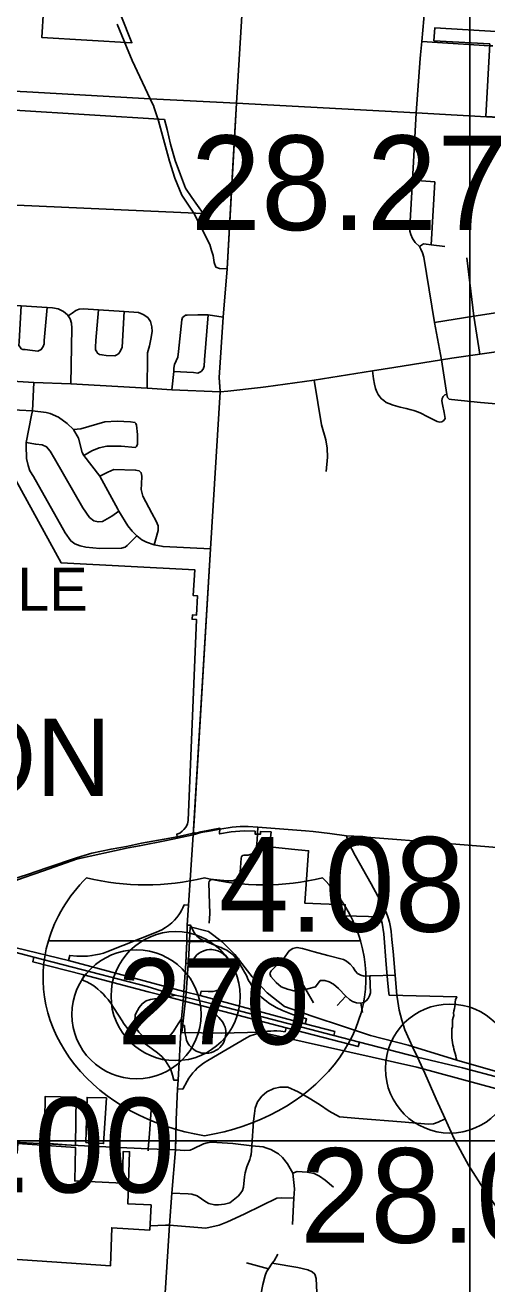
# Model space of a CAD drawing. Extents: x 1659811 to 1934326, y 644115 to 934867.
# Drawn here: x 1840906 to 1846268, y 763835 to 778471 of the extents above; entities that cross this region are included whole.
import ezdxf

# ---------------------------------------------------------------- set-up
doc = ezdxf.new("R2010")
doc.units = 0
for name, color, linetype in [('Default', 7, 'Continuous'), ('GM_X_City_Street', 7, 'Continuous'), ('GM_X_Corporation', 7, 'Continuous'), ('GM_X_Corporation_Text', 7, 'Continuous'), ('GM_X_County', 7, 'Continuous'), ('GM_X_County_Road', 7, 'Continuous'), ('GM_X_Interchange_Ramps', 7, 'Continuous'), ('GM_X_Interstate_Route', 7, 'Continuous'), ('GM_X_Interstate_Shield', 7, 'Continuous'), ('GM_X_State_Route', 7, 'Continuous'), ('GM_X_Township', 7, 'Continuous'), ('GM_X_Township_Road', 7, 'Continuous'), ('GM_X_Township_Text', 7, 'Continuous'), ('SC_Scratch1', 7, 'Continuous'), ('SH_Text', 7, 'Continuous')]:
    doc.layers.add(name, color=color, linetype=linetype)

msp = doc.modelspace()

# ---------------------------------------------------------------- linework, layer by layer
at = {"layer": 'Default'}
for centre in [(1842653, 767180), (1842199, 766968), (1845840, 766338)]:
    msp.add_circle(centre, 750, dxfattribs=at)
at = {"layer": 'GM_X_City_Street'}
for points in [[(1843361, 777564), (1843430, 778709), (1843626, 781866)], [(1845497, 778125), (1845512, 778280), (1845535, 778545), (1845550, 778898), (1845665, 780916), (1845701, 781367)], [(1842083, 778219), (1842149, 778061), (1842358, 777614)], [(1845512, 778280), (1846301, 778231), (1846340, 778229)], [(1845449, 777453), (1845493, 778084), (1845497, 778125)], [(1842402, 777520), (1842400, 777525), (1842358, 777614)], [(1843319, 776835), (1843361, 777564)], [(1845741, 774579), (1845662, 775012), (1845535, 775772), (1845521, 775824), (1845502, 775866), (1845486, 775898), (1845438, 775942), (1845404, 775990), (1845385, 776036), (1845376, 776077), (1845374, 776122), (1845405, 776668), (1845449, 777453)], [(1843251, 775637), (1843319, 776835)], [(1845621, 775918), (1845663, 776648), (1845405, 776668)], [(1843021, 775979), (1843015, 775989), (1842867, 776284), (1842796, 776391)], [(1843251, 775637), (1843165, 775642), (1843121, 775659), (1843101, 775711), (1843088, 775791), (1843071, 775852), (1843051, 775922), (1843021, 775979)], [(1845486, 775898), (1845532, 775927), (1845565, 775926), (1845621, 775918), (1845779, 775896)], [(1846187, 774646), (1846119, 775087), (1846036, 775766)], [(1843170, 774216), (1843158, 774374), (1843206, 775074), (1843251, 775637)], [(1839970, 775238), (1840262, 775243), (1840564, 775225), (1840861, 775207), (1841162, 775189), (1841222, 775185), (1841290, 775172), (1841353, 775141), (1841397, 775101), (1841404, 775090), (1841428, 775058), (1841443, 775004), (1841449, 774946), (1841435, 774301)], [(1840861, 775207), (1840838, 774791), (1840833, 774747), (1840847, 774725), (1840861, 774709), (1840880, 774698), (1840904, 774698), (1840962, 774691)], [(1840962, 774691), (1841054, 774682), (1841092, 774698), (1841116, 774734), (1841127, 774766), (1841127, 774804), (1841162, 775189)], [(1841404, 775090), (1841453, 775122), (1841493, 775154), (1841535, 775169), (1841581, 775171), (1841757, 775160), (1842056, 775141), (1842222, 775131), (1842275, 775106), (1842331, 775070), (1842360, 775025), (1842379, 774963), (1842383, 774909), (1842366, 774821), (1842349, 774743), (1842328, 774659), (1842327, 774615), (1842324, 774250)], [(1841848, 774629), (1841798, 774638), (1841770, 774642), (1841746, 774656), (1841737, 774674), (1841723, 774695), (1841721, 774727), (1841726, 774805), (1841757, 775160)], [(1841848, 774629), (1841948, 774626), (1841970, 774638), (1841994, 774655), (1842014, 774685), (1842031, 774727), (1842056, 775141)], [(1845662, 775012), (1846119, 775087), (1846575, 775157), (1846581, 775158)], [(1842611, 774230), (1842631, 774442), (1842633, 774484), (1842641, 774524), (1842678, 774611), (1842687, 774675), (1842724, 775045), (1842732, 775071), (1842748, 775085), (1842768, 775097), (1842786, 775100), (1842910, 775103), (1842994, 775104), (1843032, 775103), (1843206, 775074)], [(1842631, 774442), (1842860, 774431), (1842912, 774426), (1842950, 774442), (1842974, 774470), (1842987, 774506), (1842989, 774578), (1843032, 775103)], [(1845862, 774597), (1846187, 774646), (1846646, 774713), (1847321, 774819), (1847723, 774885)], [(1845190, 774492), (1845741, 774579), (1845862, 774597)], [(1845804, 774177), (1845741, 774579)], [(1837216, 774542), (1837230, 774542), (1837601, 774525), (1837819, 774511), (1838330, 774482), (1839378, 774411), (1839814, 774390), (1841008, 774316), (1841435, 774301), (1842324, 774250), (1842611, 774230), (1843171, 774207)], [(1843639, 774259), (1843701, 774266), (1844262, 774342), (1844940, 774452), (1845190, 774492)], [(1844940, 774452), (1844953, 774357), (1844962, 774295), (1844975, 774246), (1844991, 774206), (1845008, 774175), (1845027, 774148), (1845047, 774125), (1845071, 774105), (1845100, 774085), (1845130, 774071), (1845181, 774051), (1845262, 774029), (1845332, 774012), (1845389, 773999), (1845420, 773990), (1845476, 773970), (1845504, 773959), (1845576, 773922), (1845690, 773864), (1845724, 773856), (1845746, 773860), (1845770, 773875), (1845784, 773899), (1845772, 773968), (1845752, 774061), (1845746, 774102), (1845751, 774130), (1845760, 774155), (1845781, 774171), (1845804, 774177)], [(1840981, 773938), (1840991, 773988), (1841008, 774316)], [(1843171, 774207), (1843262, 774214), (1843639, 774259)], [(1844402, 773280), (1844416, 773448), (1844414, 773552), (1844398, 773650), (1844348, 773822), (1844262, 774342)], [(1842868, 769214), (1843058, 772381), (1843171, 774207), (1843170, 774216)], [(1847958, 773895), (1847415, 773927), (1847303, 773978), (1846755, 774028), (1846329, 774071), (1846194, 774085), (1845860, 774117), (1845831, 774124), (1845811, 774142), (1845804, 774177)], [(1841982, 772844), (1841774, 773225), (1841588, 773468), (1841569, 773501), (1841526, 773670), (1841466, 773770), (1841395, 773838), (1841292, 773914), (1841196, 773956), (1841148, 773969), (1840991, 773988), (1840688, 774003), (1840385, 774021), (1840025, 773963), (1839748, 773976)], [(1842202, 772531), (1842092, 772422), (1842066, 772402), (1842026, 772388), (1841772, 772386), (1841612, 772400), (1841546, 772415), (1841482, 772441), (1841435, 772473), (1841371, 772566), (1841002, 773221), (1840960, 773287), (1840940, 773349), (1840922, 773431), (1840917, 773582), (1840919, 773620), (1840981, 773938)], [(1841466, 773770), (1841552, 773779), (1841830, 773860), (1841976, 773866), (1842130, 773859), (1842180, 773851), (1842192, 773838), (1842200, 773818), (1842212, 773710)], [(1841588, 773468), (1841681, 773522), (1841765, 773556), (1841853, 773574), (1842021, 773575), (1842187, 773562), (1842201, 773572), (1842209, 773598), (1842212, 773710)], [(1841995, 772820), (1841912, 772760), (1841806, 772698), (1841752, 772694), (1841702, 772709), (1841654, 772745), (1841574, 772859), (1841246, 773432), (1841195, 773518), (1841155, 773569), (1841103, 773591), (1841029, 773597), (1840919, 773620)], [(1841774, 773225), (1841866, 773273), (1841937, 773305), (1842189, 773298), (1842230, 773287), (1842254, 773266), (1842260, 773227), (1842258, 773135), (1842252, 773072), (1842274, 772994), (1842376, 772798), (1842428, 772703), (1842449, 772648), (1842449, 772594), (1842404, 772427)], [(1843058, 772381), (1842508, 772407), (1842404, 772427), (1842317, 772459), (1842262, 772486), (1842202, 772531), (1842149, 772588), (1842099, 772648), (1841995, 772820), (1841982, 772844)], [(1842858, 769056), (1842868, 769214)], [(1843043, 768027), (1843050, 768143), (1843049, 768253), (1843038, 768496), (1843043, 768514), (1843055, 768528), (1843073, 768536), (1843092, 768535), (1843253, 768523), (1843320, 768520), (1843363, 768539), (1843393, 768575), (1843403, 768620), (1843414, 768783), (1843417, 768801), (1843429, 768815), (1843446, 768821), (1843496, 768818), (1843544, 768835), (1843579, 768871), (1843594, 768920), (1843599, 768997), (1843607, 769147)], [(1843166, 769121), (1843312, 769147), (1843405, 769154), (1843496, 769153), (1843607, 769147), (1844162, 769102), (1844251, 769093), (1844444, 769072), (1844638, 769046), (1844725, 769041), (1845071, 769014), (1845571, 768974)], [(1842858, 769056), (1842948, 769082), (1843068, 769103), (1843166, 769121)], [(1845234, 767120), (1845224, 767187), (1845204, 767426), (1845182, 767700), (1845167, 767840), (1845156, 767933), (1845149, 767984), (1845138, 768041), (1845122, 768091), (1845098, 768156), (1845069, 768217), (1845002, 768342), (1844925, 768485), (1844739, 768817), (1844660, 768963), (1844638, 769046)], [(1845571, 768974), (1846531, 768898), (1847239, 768842), (1847822, 768811)], [(1843749, 767443), (1843764, 767473), (1843906, 767616), (1843973, 767707), (1844015, 767736), (1844062, 767746), (1844126, 767733), (1844263, 767694), (1844421, 767652), (1844603, 767607), (1844638, 767586), (1844681, 767553), (1844716, 767513), (1844740, 767473), (1844768, 767443), (1844805, 767426), (1844845, 767414), (1844911, 767416), (1844923, 767417)], [(1843749, 767443), (1843760, 767409), (1843823, 767338), (1843879, 767288), (1843953, 767263), (1844044, 767238), (1844116, 767245), (1844168, 767259), (1844191, 767266), (1844280, 767290), (1844334, 767362), (1844386, 767361), (1844439, 767347), (1844488, 767319), (1844545, 767271), (1844632, 767180), (1844674, 767140), (1844708, 767117), (1844753, 767104), (1844804, 767100), (1844837, 767108), (1844866, 767126), (1844889, 767151), (1844907, 767184), (1844916, 767218), (1844911, 767416)], [(1844168, 767259), (1844078, 767407)], [(1844923, 767417), (1845204, 767426)], [(1844255, 767101), (1844168, 767259)], [(1844532, 767071), (1844632, 767180)], [(1844826, 766990), (1844804, 767100)], [(1845370, 766668), (1845315, 766789), (1845283, 766902), (1845252, 767019), (1845235, 767117), (1845234, 767120)], [(1842656, 765523), (1842661, 765743), (1842676, 766102), (1842682, 766202), (1842718, 766840), (1842723, 766916)], [(1846685, 763696), (1846672, 764177), (1846661, 764269), (1846648, 764320), (1846623, 764384), (1846586, 764445), (1846255, 764903), (1846054, 765215), (1845890, 765521), (1845783, 765752), (1845681, 765981), (1845547, 766286)], [(1842610, 764890), (1842799, 764881), (1842841, 764877), (1842902, 764857), (1843005, 764789), (1843040, 764770), (1843107, 764753), (1843153, 764753), (1843220, 764760), (1843282, 764776), (1843380, 764855), (1843405, 764882), (1843429, 764921), (1843442, 764959), (1843453, 765079), (1843463, 765127), (1843481, 765195), (1843516, 765282), (1843525, 765312), (1843531, 765339), (1843535, 765382), (1843540, 765439), (1843558, 765728), (1843568, 765815), (1843576, 765877), (1843603, 765952), (1843655, 766017), (1843714, 766066), (1843795, 766106), (1843868, 766123), (1843957, 766120), (1844079, 766069), (1844205, 765993), (1844326, 765919), (1844439, 765841), (1844557, 765776), (1844783, 765756), (1845275, 765720), (1845592, 765690), (1845648, 765696), (1845702, 765713), (1845783, 765752)], [(1842333, 765383), (1842335, 765406), (1842352, 765580), (1842372, 765911)], [(1840805, 765479), (1840846, 765477), (1841597, 765441)], [(1842273, 759744), (1842290, 760025), (1842411, 761872), (1842432, 762237), (1842469, 762838), (1842536, 763790), (1842583, 764517), (1842610, 764890), (1842653, 765394), (1842656, 765523)], [(1842653, 765394), (1842759, 765387), (1842824, 765391), (1842857, 765403), (1842979, 765462), (1843021, 765473), (1843070, 765481), (1843317, 765465), (1843540, 765439)], [(1841597, 765441), (1842335, 765406), (1842653, 765394)], [(1844012, 764523), (1844027, 764832), (1844035, 764939), (1844016, 765120), (1843954, 765232), (1843895, 765304), (1843850, 765345), (1843761, 765395), (1843725, 765410), (1843701, 765418), (1843671, 765427), (1843540, 765439)], [(1844016, 765120), (1844066, 765140), (1844123, 765136), (1844180, 765134), (1844263, 765118), (1844325, 765086), (1844392, 765041), (1844487, 764960)], [(1842537, 764516), (1842583, 764517), (1843004, 764483), (1843160, 764518), (1843258, 764556), (1843451, 764646), (1843657, 764745), (1843830, 764830), (1843883, 764834), (1844027, 764832)], [(1842357, 764510), (1842537, 764516)], [(1843817, 763031), (1843706, 763414), (1843656, 763585), (1843645, 763642), (1843644, 763680), (1843657, 763768), (1843666, 763828), (1843694, 763932), (1843709, 763975), (1843733, 764010), (1843777, 764075), (1843798, 764104), (1843841, 764178)], [(1843476, 764080), (1843733, 764010)], [(1843777, 764075), (1844073, 764023), (1844191, 763999), (1844241, 763976), (1844270, 763947), (1844285, 763897), (1844294, 763733)]]:
    msp.add_lwpolyline(points, dxfattribs=at)
at = {"layer": 'GM_X_Corporation'}
for points in [[(1841118, 778645), (1841099, 778328), (1842145, 778266), (1842016, 778588)], [(1846859, 778368), (1846710, 778378), (1846702, 778229), (1846625, 778234), (1846634, 778383), (1845663, 778439), (1845654, 778289), (1846303, 778254), (1846258, 777411), (1846699, 777386), (1846740, 778185), (1846816, 778181), (1846819, 778221), (1846824, 778221), (1846830, 778222), (1846834, 778223), (1846838, 778226), (1846842, 778229), (1846846, 778234), (1846848, 778239), (1846850, 778244), (1846851, 778248), (1846852, 778267)], [(1838033, 776502), (1842974, 776280), (1842842, 776467), (1842767, 776576), (1842710, 776732), (1842648, 776896), (1842594, 777087), (1842556, 777259), (1842523, 777374), (1840783, 777481), (1840533, 777392), (1840233, 777406), (1840220, 777106), (1838064, 777201)], [(1841129, 765469), (1841489, 765445), (1841500, 766005), (1841140, 766014)], [(1841611, 765479), (1841817, 765466), (1841849, 765996), (1841625, 766002)], [(1840273, 764104), (1840525, 764087), (1840531, 764137), (1841899, 764045), (1841912, 764487), (1842353, 764460), (1842368, 764753), (1842098, 764766), (1842119, 765370), (1842045, 765374), (1842037, 765007), (1841481, 765031), (1841489, 765422), (1840819, 765465), (1840812, 765355), (1840438, 765373), (1840417, 765105), (1840414, 765080), (1840340, 765083), (1840311, 764610), (1840302, 764487), (1840501, 764472), (1840497, 764422), (1840298, 764437)]]:
    msp.add_lwpolyline(points, close=True, dxfattribs=at)
for points in [[(1846475, 766277), (1845920, 766435), (1845913, 766459), (1845907, 766486), (1845902, 766512), (1845892, 766537), (1845885, 766563), (1845880, 766589), (1845872, 766614), (1845870, 766642), (1845866, 766667), (1845863, 766695), (1845863, 766746), (1845861, 766773), (1845863, 766799), (1845868, 766825), (1845868, 766878), (1845871, 766905), (1845878, 766931), (1845887, 766956), (1845883, 766982), (1845887, 767008), (1845892, 767035), (1845897, 767061), (1845901, 767086), (1845902, 767112), (1845906, 767138), (1845919, 767173), (1845133, 767192), (1845129, 767211), (1845115, 767371), (1845101, 767548), (1845073, 767906), (1845053, 768030), (1845031, 768101), (1844619, 768115), (1844624, 768242), (1844154, 768262), (1844199, 768870), (1844000, 768888), (1843746, 768916), (1843763, 769089), (1843640, 769096), (1843639, 769063), (1843576, 769064), (1843577, 769098), (1843449, 769104), (1843299, 769092), (1843165, 769066), (1843168, 769133), (1842946, 769091), (1842878, 769072), (1842877, 769080), (1842672, 769033), (1842669, 769064), (1842701, 769076), (1842729, 769098), (1842750, 769117), (1842777, 769150), (1842792, 769183), (1842799, 769223), (1842895, 771561), (1842845, 771563), (1842848, 771613), (1842898, 771611), (1842909, 771835), (1842859, 771838), (1842875, 772138), (1841326, 772218), (1840796, 773182)], [(1840690, 768517), (1840933, 768594), (1841158, 768672), (1841502, 768788), (1841682, 768841), (1841903, 768890), (1842084, 768921), (1842258, 768958), (1842521, 769004), (1842672, 769033), (1842877, 769080), (1842878, 769072), (1842946, 769091), (1843168, 769133), (1843165, 769066), (1843299, 769092), (1843449, 769104), (1843577, 769098), (1843576, 769064), (1843639, 769063), (1843640, 769096), (1843763, 769089), (1843746, 768916), (1844000, 768888), (1844199, 768870), (1844154, 768262), (1844624, 768242), (1844619, 768115), (1845031, 768101), (1845053, 768030), (1845073, 767906), (1845101, 767548), (1845115, 767371), (1845129, 767211), (1845133, 767192), (1845919, 767173), (1845906, 767138), (1845902, 767112), (1845901, 767086), (1845897, 767061), (1845892, 767035), (1845887, 767008), (1845883, 766982), (1845887, 766956), (1845878, 766931), (1845871, 766905), (1845868, 766878), (1845868, 766825), (1845863, 766799), (1845861, 766773), (1845863, 766746), (1845863, 766695), (1845866, 766667), (1845870, 766642), (1845872, 766614), (1845880, 766589), (1845885, 766563), (1845892, 766537), (1845902, 766512), (1845907, 766486), (1845913, 766459), (1845920, 766435), (1845355, 766612), (1844916, 766722), (1844614, 766823), (1844238, 766948), (1843917, 767058), (1843717, 767218), (1843542, 767405), (1843341, 767663), (1843196, 767812), (1843037, 767931), (1842824, 767987), (1842807, 767664), (1842774, 767167), (1842727, 766758), (1843183, 766749), (1843641, 766763), (1845456, 766355), (1848555, 765514)]]:
    msp.add_lwpolyline(points, dxfattribs=at)
at = {"layer": 'GM_X_County'}
for points in [[(1840611, 777712), (1840924, 777694), (1842358, 777614), (1843361, 777564), (1845449, 777453), (1847560, 777333), (1848085, 777300), (1848276, 777289), (1848580, 777271), (1850569, 777151), (1850744, 777141), (1850903, 777132), (1851193, 777116), (1851228, 777114), (1853977, 776957), (1854746, 776908), (1855849, 776844), (1860837, 776510)], [(1860837, 776510), (1855849, 776844), (1854746, 776908), (1853977, 776957), (1851228, 777114), (1851193, 777116), (1850903, 777132), (1850744, 777141), (1850569, 777151), (1848580, 777271), (1848276, 777289), (1848085, 777300), (1847560, 777333), (1845449, 777453), (1843361, 777564), (1842358, 777614), (1840924, 777694), (1840611, 777712)]]:
    msp.add_lwpolyline(points, dxfattribs=at)
at = {"layer": 'GM_X_County_Road'}
msp.add_lwpolyline([(1845547, 766286), (1845524, 766336), (1845462, 766471), (1845405, 766592), (1845370, 766668)], dxfattribs=at)
at = {"layer": 'GM_X_Interchange_Ramps'}
for points in [[(1842802, 768238), (1842752, 768241), (1842739, 768209), (1842725, 768182), (1842708, 768150), (1842691, 768125), (1842668, 768094), (1842642, 768064), (1842608, 768031), (1842572, 768001), (1842537, 767977), (1842492, 767952), (1842430, 767925), (1841855, 767694), (1841815, 767681), (1841771, 767669), (1841721, 767659), (1841681, 767652), (1841631, 767647), (1841596, 767645), (1841551, 767644), (1841506, 767646), (1841423, 767653), (1841408, 767595)], [(1844160, 766860), (1844174, 766915), (1844013, 766968), (1843896, 767015), (1843820, 767050), (1843738, 767100), (1843708, 767121), (1843681, 767143), (1843650, 767170), (1843620, 767200), (1843600, 767222), (1843576, 767250), (1843558, 767275), (1843536, 767306), (1843518, 767336), (1843502, 767363), (1843489, 767389), (1843479, 767412), (1843396, 767558), (1843384, 767579), (1843368, 767604), (1843351, 767626), (1843328, 767651), (1843311, 767667), (1843291, 767684), (1843268, 767700), (1843249, 767713), (1843228, 767724), (1843203, 767736), (1843181, 767745), (1843156, 767753), (1842986, 767822), (1842960, 767835), (1842940, 767846), (1842920, 767861), (1842901, 767878), (1842886, 767895), (1842869, 767919), (1842858, 767938), (1842827, 768004), (1842788, 768006)], [(1842986, 767822), (1842981, 767812), (1842819, 767814), (1842782, 767813)], [(1844491, 766721), (1844503, 766768), (1844160, 766860), (1842937, 767186), (1842750, 767236), (1841408, 767595), (1840801, 767742), (1840787, 767690)], [(1842773, 767562), (1842828, 767559), (1842860, 767610), (1842875, 767631), (1842897, 767656), (1842918, 767676), (1842946, 767693), (1842980, 767708), (1843018, 767718), (1843046, 767721), (1843073, 767721), (1843114, 767716), (1843144, 767707), (1843179, 767691), (1843207, 767672), (1843238, 767645), (1843268, 767606), (1843288, 767565), (1843298, 767531), (1843304, 767489), (1843301, 767443), (1843292, 767402), (1843276, 767365), (1843257, 767333), (1843238, 767311), (1843210, 767285), (1843181, 767266), (1843155, 767253), (1843121, 767241), (1843090, 767235), (1843031, 767234), (1842952, 767240), (1842937, 767186)], [(1841008, 767632), (1840994, 767581), (1841586, 767427), (1842333, 767232), (1842562, 767172), (1842742, 767125), (1843125, 767025), (1843938, 766812), (1844775, 766594), (1844788, 766645)], [(1841586, 767427), (1841571, 767367), (1841624, 767345), (1841658, 767326), (1841690, 767306), (1841721, 767284), (1841751, 767261), (1841784, 767232), (1841811, 767206), (1841841, 767174), (1841869, 767141), (1841887, 767117), (1841908, 767087), (1841925, 767060), (1841938, 767037), (1842032, 766894), (1842049, 766866), (1842068, 766838), (1842086, 766814), (1842112, 766782), (1842137, 766754), (1842161, 766730), (1842190, 766703), (1842216, 766682), (1842248, 766658), (1842274, 766640), (1842313, 766617), (1842444, 766520), (1842469, 766499), (1842492, 766478), (1842514, 766455), (1842536, 766428), (1842557, 766398), (1842576, 766366), (1842593, 766333), (1842602, 766312), (1842610, 766289), (1842619, 766261), (1842632, 766205), (1842682, 766202)], [(1843125, 767025), (1843109, 766971), (1843135, 766950), (1843154, 766933), (1843180, 766906), (1843202, 766877), (1843215, 766852), (1843228, 766818), (1843236, 766782), (1843237, 766738), (1843231, 766698), (1843218, 766658), (1843205, 766631), (1843190, 766609), (1843168, 766584), (1843146, 766565), (1843126, 766551), (1843097, 766536), (1843070, 766526), (1843040, 766519), (1842996, 766516), (1842960, 766519), (1842926, 766528), (1842892, 766542), (1842866, 766558), (1842846, 766574), (1842829, 766591), (1842811, 766612), (1842796, 766635), (1842781, 766667), (1842771, 766709), (1842765, 766740), (1842760, 766774), (1842756, 766838), (1842718, 766840)], [(1842676, 766102), (1842737, 766099), (1842787, 766193), (1842808, 766226), (1842831, 766258), (1842854, 766287), (1842880, 766316), (1842909, 766345), (1842943, 766374), (1842978, 766400), (1843028, 766431), (1843477, 766697), (1843519, 766717), (1843568, 766736), (1843603, 766747), (1843641, 766757), (1843681, 766765), (1843722, 766771), (1843759, 766774), (1843793, 766776), (1843831, 766775), (1843876, 766772), (1843926, 766766), (1843938, 766812)]]:
    msp.add_lwpolyline(points, dxfattribs=at)
at = {"layer": 'GM_X_Interstate_Route'}
for points in [[(1840787, 767690), (1841008, 767632)], [(1841008, 767632), (1842323, 767292), (1842546, 767222)], [(1842546, 767222), (1842648, 767190), (1842746, 767174)], [(1842746, 767174), (1842846, 767149)], [(1842846, 767149), (1843140, 767077), (1844491, 766721)], [(1844491, 766721), (1844788, 766645)], [(1844788, 766645), (1845462, 766471), (1845988, 766345), (1847736, 765880), (1848451, 765692), (1848529, 765671)]]:
    msp.add_lwpolyline(points, dxfattribs=at)
at = {"layer": 'GM_X_Interstate_Shield'}
msp.add_line((1844802, 767822), (1841176, 767822), dxfattribs=at)
msp.add_line((1844802, 767822), (1841176, 767822), dxfattribs=at)
for centre, start_param, end_param in [((1843457, 767394), 2.47259, 2.911027), ((1842304, 770350), 4.415841, 5.008937), ((1843674, 770350), 4.415841, 5.008937), ((1842520, 767394), 0.230566, 0.669003), ((1843457, 767394), 2.911027, 4.511031), ((1842520, 767394), 4.913747, 6.513751)]:
    msp.add_ellipse(centre, major_axis=(2344, 0), ratio=0.8, start_param=start_param, end_param=end_param, dxfattribs=at)
at = {"layer": 'GM_X_State_Route'}
for points in [[(1838658, 767760), (1838732, 767772), (1838801, 767797), (1838915, 767820), (1838989, 767851), (1839355, 768061), (1839591, 768205), (1839743, 768271), (1839874, 768308), (1839991, 768337), (1840219, 768345), (1840296, 768354), (1840382, 768368), (1840465, 768400), (1840690, 768485), (1840896, 768559), (1841120, 768639), (1841502, 768772), (1842103, 768904), (1842233, 768930), (1842548, 768991), (1842858, 769056)], [(1842858, 769056), (1842802, 768238), (1842788, 768006), (1842782, 767813), (1842779, 767742)], [(1842779, 767742), (1842773, 767562), (1842750, 767236), (1842746, 767174), (1842742, 767125), (1842723, 766916)], [(1842723, 766916), (1842683, 766860), (1842626, 766764), (1842579, 766712), (1842536, 766685), (1842490, 766667), (1842411, 766658), (1842373, 766663), (1842300, 766701), (1842268, 766719), (1842225, 766760), (1842193, 766812), (1842178, 766884), (1842185, 766961), (1842209, 767014), (1842230, 767047), (1842264, 767091), (1842313, 767124), (1842361, 767141), (1842409, 767149), (1842502, 767159), (1842562, 767172), (1842648, 767190)]]:
    msp.add_lwpolyline(points, dxfattribs=at)
at = {"layer": 'GM_X_Township'}
for points in [[(1843361, 777564), (1843430, 778709), (1843626, 781866), (1843694, 782979), (1843719, 783387), (1843850, 785510), (1843918, 786568), (1844278, 791160)], [(1842536, 763790), (1842583, 764517), (1842610, 764890), (1842653, 765394), (1842661, 765743), (1842676, 766102), (1842682, 766202), (1842718, 766840), (1842723, 766916), (1842742, 767125), (1842746, 767174), (1842750, 767236), (1842773, 767562), (1842782, 767813), (1842788, 768006), (1842802, 768238), (1842858, 769056), (1843058, 772381), (1843171, 774207), (1843158, 774374), (1843206, 775074), (1843251, 775637), (1843361, 777564)]]:
    msp.add_lwpolyline(points, dxfattribs=at)
at = {"layer": 'GM_X_Township_Road'}
for points in [[(1841974, 778482), (1842083, 778219)], [(1842796, 776391), (1842726, 776493), (1842643, 776693), (1842583, 776889), (1842454, 777357), (1842402, 777520)]]:
    msp.add_lwpolyline(points, dxfattribs=at)
at = {"layer": 'SC_Scratch1'}
msp.add_lwpolyline([(1729596, 899996), (1925846, 899996), (1925846, 765496), (1729596, 765496)], close=True, dxfattribs=at)
at = {"layer": 'SH_Text'}
msp.add_lwpolyline([(1741462, 842026), (1846073, 842026), (1846073, 754070), (1741462, 754070)], close=True, dxfattribs=at)

# ---------------------------------------------------------------- texts
at = {"layer": 'Default'}
for s, p in [('28.27', (1842828, 776088)), ('4.08', (1843154, 767930)), ('4.00', (1839782, 764897)), ('28.00', (1844099, 764312))]:
    msp.add_text(s, height=1100, dxfattribs=at).set_placement(p)
at = {"layer": 'GM_X_Corporation_Text'}
msp.add_text('WESTERVILLE', height=500, rotation=0, dxfattribs=at).set_placement((1836951, 771662))
at = {"layer": 'GM_X_Interstate_Shield'}
msp.add_text('270', height=1000, dxfattribs=at).set_placement((1841979, 766619))
at = {"layer": 'GM_X_Township_Text'}
msp.add_text('SHARON', height=900, rotation=0, dxfattribs=at).set_placement((1836755, 769508))

doc.saveas('drawing.dxf')
